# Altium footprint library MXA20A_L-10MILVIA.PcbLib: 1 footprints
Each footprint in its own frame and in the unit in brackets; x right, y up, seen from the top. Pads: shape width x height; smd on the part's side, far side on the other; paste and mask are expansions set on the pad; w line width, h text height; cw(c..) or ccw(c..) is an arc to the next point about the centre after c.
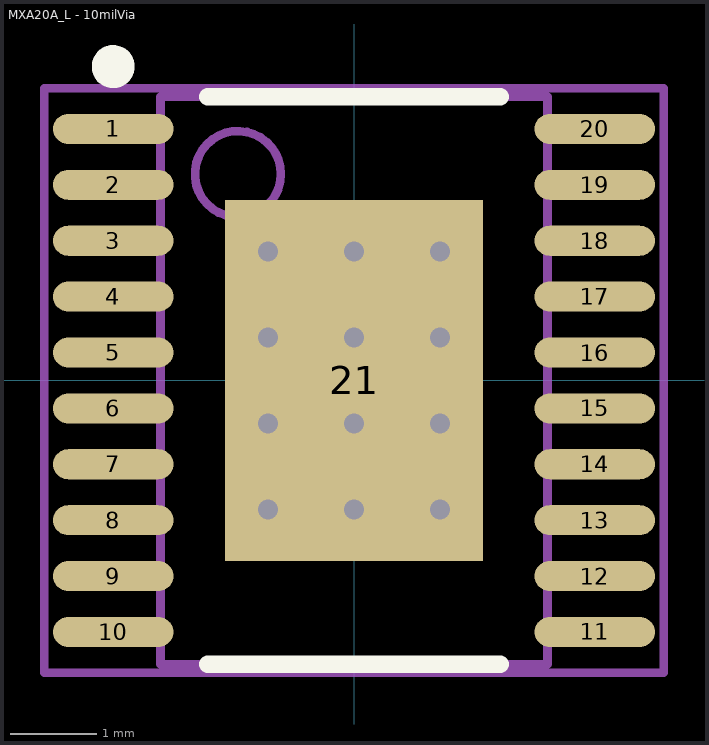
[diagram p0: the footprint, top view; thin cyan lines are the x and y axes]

## MXA20A_L - 10milVia [mm] "TSOP, 20-Leads, Body 6.5x4.4mm, Pitch 0.65mm, Exposed Pad, IPC High Density"
height 1.1
pads (21):
  oval 1.4x0.35 smd: 1(-2.8,2.925) 2(-2.8,2.275) 3(-2.8,1.625) 4(-2.8,0.975) 5(-2.8,0.325) 6(-2.8,-0.325) 7(-2.8,-0.975) 8(-2.8,-1.625) 9(-2.8,-2.275) 10(-2.8,-2.925) 11(2.8,-2.925) 12(2.8,-2.275) 13(2.8,-1.625) 14(2.8,-0.975) 15(2.8,-0.325) 16(2.8,0.325) 17(2.8,0.975) 18(2.8,1.625) 19(2.8,2.275) 20(2.8,2.925)
  rect 3x4.2 smd: 21(0,0)
via 0,0.5 diameter 0.584 hole 0.229
via 1,0.5 diameter 0.584 hole 0.229
via 0,-0.5 diameter 0.584 hole 0.229
via 1,-0.5 diameter 0.584 hole 0.229
via 0,-1.5 diameter 0.584 hole 0.229
via 1,-1.5 diameter 0.584 hole 0.229
via -1,-1.5 diameter 0.584 hole 0.229
via -1,-0.5 diameter 0.584 hole 0.229
via -1,0.5 diameter 0.584 hole 0.229
via -1,1.5 diameter 0.584 hole 0.229
via 1,1.5 diameter 0.584 hole 0.229
via 0,1.5 diameter 0.584 hole 0.229
Top Overlay:
  circle w0.25: c-2.8,3.65 r0.125
  lines w0.2: -1.7,-3.3 1.7,-3.3 ; -1.7,3.3 1.7,3.3
M5 Assembly Top:
  text ".Designator" at -1.524,-0.508 h1.02
M13 Component Bodies Top:
  circle w0.1: c-1.35,2.4 r0.5
  lines w0.1: -2.25,-3.3 -2.25,3.3 2.25,3.3 2.25,-3.3 -2.25,-3.3
M15  Courtyards Top:
  lines w0.1: -0.5,0 0.5,0 ; 0,-0.5 0,0.5 ; -3.6,-3.4 -3.6,3.4 3.6,3.4 3.6,-3.4 -3.6,-3.4
3D body: height 1.1, standoff 0, extent -2.25,-3.3 2.25,3.3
